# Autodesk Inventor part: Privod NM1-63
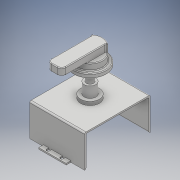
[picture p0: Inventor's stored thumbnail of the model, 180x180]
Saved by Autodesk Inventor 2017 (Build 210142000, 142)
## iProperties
Part Number: Privod NM1-63
Material: Типовые
Document SubType Name: Modeling
Designer: RSagdiev
Density: 1 g/cm^3
Appearance: По умолчанию
Author: RSagdiev
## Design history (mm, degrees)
sketch "Эскиз1"
  geometry: L1 (-19, 52)-(19, 52); L2 (19, 52)-(19, 43.5); L3 (19, 43.5)-(11.5, 43.5); L4 (-19, 43.5)-(-19, 52); L5 (0, 0)-(119.698, 0); L6 (0, 0)-(-104.809, 0); L7 (0, 94.88)-(0, -60.954); L8 (-11.5, 43.5)-(-7.5, 43.5); L9 (-7.5, 43.5)-(-7.5, 48.5); L10 (-9.5, 50.5)-(-9.5, 50.5); L11 (-11.5, 48.5)-(-11.5, 43.5); L12 (7.5, 43.5)-(7.5, 48.5); L13 (9.5, 50.5)-(9.5, 50.5); L14 (11.5, 43.5)-(7.5, 43.5); L15 (11.5, 48.5)-(11.5, 43.5); L16 (-11.5, 43.5)-(-19, 43.5); L17 (-7.5, 43.5)-(-11.5, 43.5); L18 (7.5, 43.5)-(-7.5, 43.5); L19 (11.5, 43.5)-(7.5, 43.5); A1 r 2 centre (-9.5, 48.5) between (-9.5, 50.5) and (-11.5, 48.5); A2 r 2 centre (-9.5, 48.5) between (-7.5, 48.5) and (-9.5, 50.5); A3 r 2 centre (9.5, 48.5) between (9.5, 50.5) and (7.5, 48.5); A4 r 2 centre (9.5, 48.5) between (11.5, 48.5) and (9.5, 50.5); 5 further points
  constraints: 38 end point, 10 point on line, 10 symmetric about line, 8 parallel, 8 point on circle, 4 centre point, 4 horizontal, 4 tangent, 2 perpendicular, 1 concentric, 1 midpoint, 1 vertical, 2 other
  dimensions: "d0" = 43.5 distance between parallel lines of L3 L6 (= 0.5 x Высота); "d1" = 8.5 distance of L1.end L2.end; "d2" = 38 distance between parallel lines of L2 L4 (= 0.5 x Ширина); "d3" = 4 distance of point (-11.5, 50.5) point (-7.5, 50.5); "d4" = 7 distance of point (-7.5, 50.5) L8.end; "d5" = 2 radius of A1 (derived); "d6" = 9.5 distance from line of L4 A1.centre (= 0.25 x d2)
extrude "Выдавливание1" new body sketch "Эскиз1" distance "d7" = 2; taper "d8" = 0 deg
mirror "Зеркальное отражение1"
sketch "Эскиз2"
  geometry: L1 (-19, 52)-(-19, 43.5) reference; L2 (19, 43.5)-(19, 52) reference; L3 (-19, -52)-(-19, -43.5) reference; L4 (19, -43.5)-(19, -52) reference; L5 (-38, 45.5)-(38, 45.5); L6 (38, 45.5)-(38, 43.5); L7 (38, 43.5)-(-38, 43.5); L8 (-38, 43.5)-(-38, 45.5); L9 (-19, 43.5)-(-11.5, 43.5) reference
  constraints: 8 end point, 2 parallel, 1 collinear, 1 horizontal, 1 perpendicular
  dimensions: "d13" = 76 distance of L5.start L5.end (= Ширина); "d14" = 2 distance of L5.end L6.end; "d15" = 19 distance between parallel lines of L1 L8 (= 0.25 x d13)
extrude "Выдавливание2" join sketch "Эскиз2" distance "d11" = 45 (computed from H1); taper "d12" = 0 deg
mirror "Зеркальное отражение2"
sketch "Эскиз3"
  geometry: L1 (-38, 45.5)-(-19, 45.5) reference; L2 (38, -45.5)-(-38, -45.5) reference; L3 (-38, 45.5)-(38, 45.5); L4 (38, 45.5)-(38, -45.5); L5 (38, -45.5)-(-38, -45.5); L6 (-38, -45.5)-(-38, 45.5); 1 further point
  constraints: 8 end point, 2 parallel, 1 horizontal, 1 perpendicular
extrude "Выдавливание3" join sketch "Эскиз3" distance "d16" = 2; taper "d17" = 0 deg
fillet "Сопряжение1" dims "d18" = 2
sketch "Эскиз4"
  geometry: L1 (38, -41.5)-(-38, -41.5) reference; L2 (38, -41.5)-(38, 41.5) reference; L3 (-38, 41.5)-(38, 41.5) reference; L4 (-38, 41.5)-(-38, -41.5) reference; L5 (-38, 41.5)-(-38, -41.5) reference; L6 (-38, -41.5)-(38, 41.5); L7 (38, -41.5)-(38, 41.5) reference; L8 (-38, 41.5)-(38, -41.5); C1 r 5 at (0, 0); 1 further point
  constraints: 4 end point, 1 centre point, 1 coincident
  dimensions: "d19" = 10 diameter of C1
extrude "Выдавливание4" cut sketch "Эскиз4" distance "d20" = 10; taper "d21" = 0 deg
sketch "Эскиз5"
  geometry: C1 r 5 at (0, 0) reference; C2 r 5 at (0, 0); C3 r 8 at (0, 0); 1 further point
  constraints: 2 centre point, 2 coincident
  dimensions: "d22" = 16 diameter of C3
extrude "Выдавливание5" new body sketch "Эскиз5" distance "d23" = 16.33333 (= 0.333333 x H1); taper "d24" = 0 deg
sketch "Эскиз6"
  geometry: C1 r 5 at (0, 0) reference; C2 r 5 at (0, 0); 1 further point
  constraints: 1 centre point, 1 coincident
extrude "Выдавливание6" new body sketch "Эскиз6" distance "d25" = 66.33333 (computed from H1); taper "d26" = 0 deg
sketch "Эскиз7"
  geometry: C1 r 5 at (0, 0) reference; C2 r 13 at (0, 0); C3 r 8 at (0, 0); C4 r 5 at (0, 0); 1 further point
  constraints: 3 centre point, 3 coincident
  dimensions: "d27" = 26 diameter of C2; "d28" = 16 diameter of C3; "d29" = 10 diameter of C4
extrude "Выдавливание7" new body sketch "Эскиз7" distance "d30" = 5; taper "d31" = 0 deg
extrude "Выдавливание8" join sketch "Эскиз7" distance "d32" = 20; taper "d33" = 0 deg
sketch "Эскиз8"
  geometry: C1 r 7 at (0, 0); 1 further point
  constraints: 1 centre point, 1 coincident
  dimensions: "d34" = 14 diameter of C1
extrude "Выдавливание9" new body sketch "Эскиз8" distance "d35" = 3; taper "d36" = 0 deg
fillet "Сопряжение2" dims "d37" = 3
sketch "Эскиз9"
  geometry: L1 (1, 13.17)-(-1, 13.17); L2 (-1, 13.17)-(-1, -13.17); L3 (-1, -13.17)-(1, -13.17); L4 (1, -13.17)-(1, 13.17); L5 (1, 13.17)-(-1, -13.17); L6 (-1, 13.17)-(1, -13.17); L7 (17.109, -1)-(-17.109, -1); L8 (-17.109, -1)-(-17.109, 1); L9 (-17.109, 1)-(17.109, 1); L10 (17.109, 1)-(17.109, -1); L11 (17.109, -1)-(-17.109, 1); L12 (-17.109, -1)-(17.109, 1); C1 r 4 at (0, 0) reference; C2 r 5 at (0, 0) reference; 1 further point
  constraints: 24 end point, 4 midpoint, 4 parallel, 2 horizontal, 2 perpendicular
  dimensions: "d38" = 2 distance of L3.end L2.end; "d39" = 2 distance of L7.end L8.end
extrude "Выдавливание10" cut sketch "Эскиз9" distance "d40" = 1; taper "d41" = 0 deg
sketch "Эскиз10"
  geometry: C1 r 17.5 at (0, 0); A1 r 4 centre (0, 0) between (1, -3.873) and (3.873, -1) reference; 1 further point
  constraints: 1 centre point, 1 coincident
  dimensions: "d42" = 35 diameter of C1
extrude "Выдавливание11" new body sketch "Эскиз10" distance "d43" = 6; taper "d44" = 0 deg; dims "d48" = 3, "d49" = 0
sketch "Эскиз11"
  geometry: C1 r 7 at (0, 0); C2 r 22.5 at (0, 0); 1 further point
  constraints: 2 centre point, 1 coincident
  dimensions: "d45" = 45 diameter of C2
extrude "Выдавливание12" join sketch "Эскиз11" distance "d46" = 6; taper "d47" = 0 deg
sketch "Эскиз12"
  geometry: L1 (-4, -49.361)-(4, -49.361); L2 (10, -43.361)-(10, 10.738); L3 (-10, 10.738)-(-10, -43.361); L4 (-10, -49.361)-(10, 14.361); L5 (10, -49.361)-(-10, 14.361); L6 (-12, 12.738)-(12, 12.738); A1 r 17.5 centre (0, 0) between (10, 14.361) and (0, -17.5) reference; A2 r 17.5 centre (0, 0) between (10, 14.361) and (0, -17.5) reference; A3 r 6 centre (-4, -43.361) between (-10, -43.361) and (-4, -49.361); A4 r 6 centre (4, -43.361) between (4, -49.361) and (10, -43.361); A5 r 2 centre (-12, 10.738) between (-10, 10.738) and (-12, 12.738); A6 r 2 centre (12, 10.738) between (12, 12.738) and (10, 10.738); A7 r 17.5 centre (0, 0) between (12, 12.738) and (-12, 12.738)
  constraints: 16 point on circle, 12 end point, 8 tangent, 6 point on line, 5 centre point, 2 equal radius, 2 horizontal, 2 midpoint, 1 coincident, 1 parallel, 1 perpendicular
  dimensions: "d63" = 20 distance of L4.end L5.end; "d64" = 6 radius of A3; "d66" = 10 distance from line of A1.centre L3; "d67" = 2 radius of A5; "d68" = 2 radius of A6 (derived)
extrude "Выдавливание13" join sketch "Эскиз12" distance "d55" = 10; taper "d56" = 0 deg
fillet "Сопряжение9" dims "d69" = 1
fillet "Сопряжение10" dims "d70" = 1
node "Твердое тело1"
node "Спроецированная петля1"
node "Твердое тело2"
node "Твердое тело3"
node "Твердое тело4"
node "Твердое тело5"
node "Спроецированная петля2"
node "Твердое тело6"
node "Спроецированная петля3"
other parameters: "H1" = 49 [user parameter; used in 3 equation terms], "Высота" = 87 [user parameter; used in 1 equation term], "Ширина" = 76 [user parameter; used in 2 equation terms]
